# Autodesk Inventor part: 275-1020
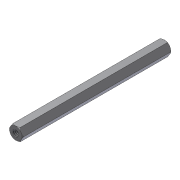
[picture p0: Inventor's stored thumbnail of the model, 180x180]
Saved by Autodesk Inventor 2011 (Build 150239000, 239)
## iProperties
Company: Autodesk Inc.
Created: 2005-07
Part Number: 275-1020
Document SubType Name: Modeling
Designer: Autodesk Inc.
Density: 1 g/cm^3
Catalog Web Link: http://www.vexrobotics.com/products/accessories/structure/standoffs-8-32.html
Description: A standoff is used in mechanics and electronics to separate two parts from one another. All VEX Standoffs have 8-32 threads.
Vendor: Innovation First, Inc.
Author: Autodesk Inc.
Title: VEX Robotics Kit of Parts
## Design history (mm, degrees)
sketch "Sketch1"
  geometry: L1 (1.955, -3.175)-(-1.711, -3.175); L2 (-1.711, -3.175)-(-3.544, 0); L3 (-3.544, 0)-(-1.711, 3.175); L4 (-1.711, 3.175)-(1.955, 3.175); L5 (1.955, 3.175)-(3.788, 0); L6 (3.788, 0)-(1.955, -3.175); 1 further point
  constraints: 12 end point, 1 horizontal, 11 other
  dimensions: "d0" = 6.35 distance between parallel lines of L1 L4
extrude "Extrusion1" new body sketch "Sketch1" distance "d1" = 76.2; taper "d2" = 0 deg
workplane "Work Plane1"
sketch "Sketch3"
  geometry: L1 (-1.325, 0)-(4.974, 0); L2 (5.482, -0.508)-(5.482, -75.692); L3 (4.974, -76.2)-(-1.325, -76.2); L4 (-1.833, -75.692)-(-1.833, -0.508); L5 (-1.833, -0.508)-(-1.325, 0); L6 (4.974, 0)-(5.482, -0.508); L7 (-1.325, -76.2)-(-1.833, -75.692); L8 (5.482, -75.692)-(4.974, -76.2); L9 (-1.833, 0)-(-1.833, -76.2) reference; L10 (3.666, 0)-(5.499, 0) reference; L11 (1.825, 0)-(1.825, -76.2); 4 further points
  constraints: 18 end point, 8 point on line, 2 midpoint, 2 parallel, 1 horizontal, 1 perpendicular
  dimensions: "d5" = 0.508 distance of L4.end point (-1.833, 0); "d6" = 0.508 distance of L1.start point (-1.833, 0) (= d5); "d7" = 0.508 distance of L1.end point (5.482, 0) (= d5); "d8" = 0.508 distance of L2.start point (5.482, 0) (= d7); "d9" = 0.508 distance of L3.end point (-1.833, -76.2) (= d5); "d10" = 0.508 distance of L4.start point (-1.833, -76.2) (= d9); "d11" = 0.508 distance of L2.end point (5.482, -76.2) (= d5); "d12" = 0.508 distance of L3.start point (5.482, -76.2) (= d11); "d13" = 7.3152 distance between parallel lines of L2 L4; "d14" = 0 distance between parallel lines of L9 L4; "d15" = 76.2 distance between parallel lines of L1 L3; "d16" = 0 distance between parallel lines of L1 L10
revolve "Revolution1" sketch "Sketch3" stored, may be unused: angle "d17" = 90 deg
sketch "Sketch5"
  geometry: C1 r 3.15 at (0, 0) reference; 1 further point
  constraints: 1 coincident
hole "Hole2" sketch "Sketch5" at (0, 0) diameter "d25" = 3.302; stored, may be unused: countersink angle "d29" = 82 deg, drill point angle "d31" = 118 deg; dims "d26" = 12.7, "d27" = 9.525, "d28" = 6.35, "d30" = 12.7
sketch "Sketch6"
  geometry: C1 r 3.15 at (0, 0) reference; 1 further point
  constraints: 1 coincident
hole "Hole3" sketch "Sketch6" at (0, 0) diameter "d32" = 3.302; stored, may be unused: countersink angle "d36" = 82 deg, drill point angle "d38" = 118 deg; dims "d33" = 12.7, "d34" = 9.525, "d35" = 6.35, "d37" = 12.7
body "Solid1"
other parameters: "d4" = -3.175
